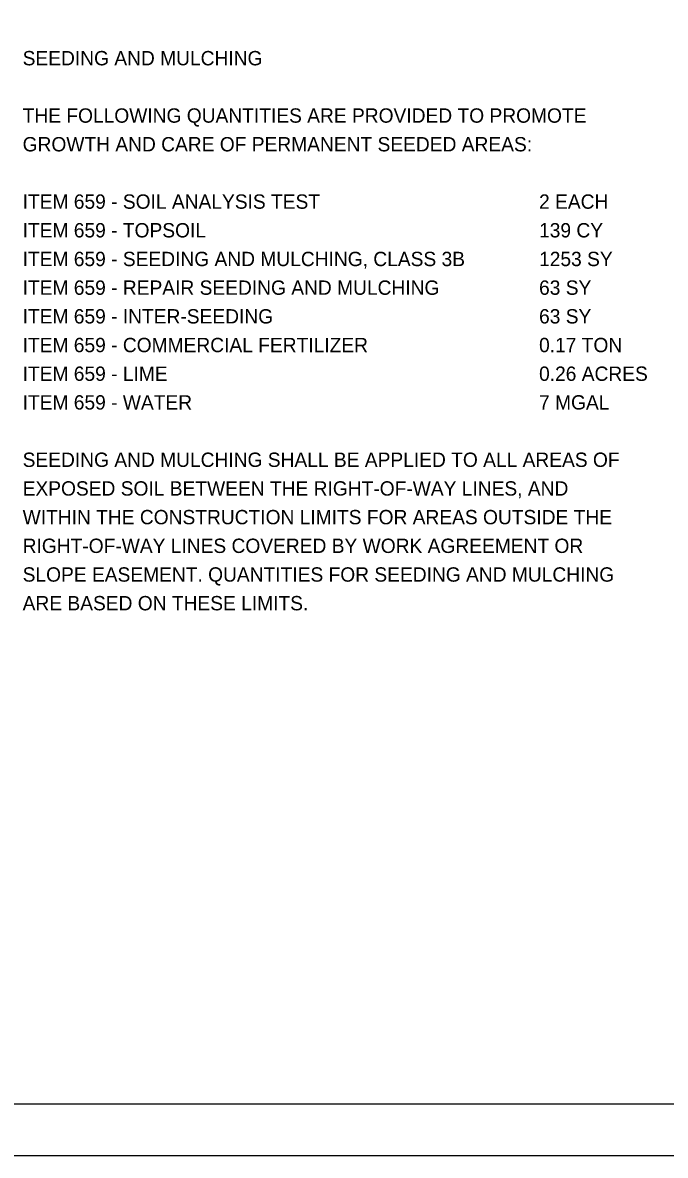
# Model space of a CAD drawing. Extents: x 0 to 34, y 0 to 22.
# Drawn here: x 17.24 to 23.51, y 0 to 11.06 of the extents above; entities that cross this region are included whole.
import ezdxf

# ---------------------------------------------------------------- set-up
doc = ezdxf.new("R2010")
doc.units = 0
for name, color, linetype in [('SH_Border', 7, 'Continuous'), ('SH_Cut_Line', 7, 'Continuous'), ('SH_Text', 7, 'Continuous')]:
    doc.layers.add(name, color=color, linetype=linetype)

msp = doc.modelspace()

# ---------------------------------------------------------------- linework, layer by layer
at = {"layer": 'SH_Border'}
msp.add_lwpolyline([(1.5, 21.5), (33.5, 21.5), (33.5, 0.5), (1.5, 0.5)], close=True, dxfattribs=at)
at = {"layer": 'SH_Cut_Line'}
msp.add_lwpolyline([(0, 0), (34, 0), (34, 22), (0, 22)], close=True, dxfattribs=at)

# ---------------------------------------------------------------- texts
at = {"layer": 'SH_Text'}
for s, p in [('SEEDING AND MULCHING', (17.24, 10.64)), ('THE FOLLOWING QUANTITIES ARE PROVIDED TO PROMOTE ', (17.24, 10.08)), ('GROWTH AND CARE OF PERMANENT SEEDED AREAS: ', (17.24, 9.8)), ('ITEM 659 - SOIL ANALYSIS TEST', (17.24, 9.24)), ('2 EACH', (22.28, 9.24)), ('ITEM 659 - TOPSOIL ', (17.24, 8.96)), ('139 CY', (22.28, 8.96)), ('ITEM 659 - SEEDING AND MULCHING, CLASS 3B', (17.24, 8.68)), ('1253 SY', (22.28, 8.68)), ('ITEM 659 - REPAIR SEEDING AND MULCHING', (17.24, 8.4)), ('63 SY', (22.28, 8.4)), ('ITEM 659 - INTER-SEEDING', (17.24, 8.12)), ('63 SY', (22.28, 8.12)), ('ITEM 659 - COMMERCIAL FERTILIZER', (17.24, 7.84)), ('0.17 TON', (22.28, 7.84)), ('ITEM 659 - LIME', (17.24, 7.56)), ('0.26 ACRES', (22.28, 7.56)), ('ITEM 659 - WATER', (17.24, 7.28)), ('7 MGAL', (22.28, 7.28)), ('SEEDING AND MULCHING SHALL BE APPLIED TO ALL AREAS OF ', (17.24, 6.72)), ('EXPOSED SOIL BETWEEN THE RIGHT-OF-WAY LINES, AND ', (17.24, 6.44)), ('WITHIN THE CONSTRUCTION LIMITS FOR AREAS OUTSIDE THE ', (17.24, 6.16)), ('RIGHT-OF-WAY LINES COVERED BY WORK AGREEMENT OR ', (17.24, 5.88)), ('SLOPE EASEMENT. QUANTITIES FOR SEEDING AND MULCHING ', (17.24, 5.6)), ('ARE BASED ON THESE LIMITS.', (17.24, 5.32))]:
    msp.add_text(s, height=0.14, dxfattribs=at).set_placement(p)

doc.saveas('drawing.dxf')
